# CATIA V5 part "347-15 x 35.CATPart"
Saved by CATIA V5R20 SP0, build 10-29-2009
Part number: 347-15 x 35
Definition: NONE
Nomenclature: 347-15 x 35
Source: Unknown
Description: 347-15 x 35
Bounding box of the stored display mesh (mm): x 0 to 35, y -13 to 13, z -13 to 13
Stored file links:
  C:\Users\Utente\Desktop\IO LAVORO\3D X SITO CF\X SITO\3D files 347\347-15 x 35.CATPart
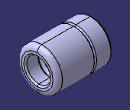
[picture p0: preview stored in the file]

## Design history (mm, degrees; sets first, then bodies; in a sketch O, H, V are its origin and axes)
Body1 "347-15 x 35" (main body)
  Solid1: solid without history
